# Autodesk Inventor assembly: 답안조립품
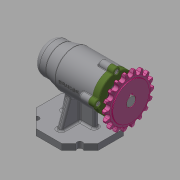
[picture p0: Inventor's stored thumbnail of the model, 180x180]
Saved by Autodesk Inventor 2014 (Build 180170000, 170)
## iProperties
Created: 2021-01
Part Number: 답안조립품
Document SubType Name: Assembly
Designer: kh
Author: kh
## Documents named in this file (12)
- C:\Users\kh\Desktop\710106V1023\답안조립품.iam
- C:\Users\kh\Desktop\710106V1023\본체.ipt
- C:\Users\kh\Desktop\710106V1023\스프로킷.ipt
- C:\Users\kh\Desktop\710106V1023\어댑터슬리브.ipt
- C:\Users\kh\Desktop\710106V1023\오일 실.ipt
- C:\Users\kh\Desktop\710106V1023\축.ipt
- C:\Users\kh\Desktop\710106V1023\커버.ipt
- C:\Users\kh\Desktop\710106V1023\키 5 x 5 x 14.ipt
- C:\Users\kh\Desktop\710106V1023\베어링 6004.ipt
- C:\Users\kh\Desktop\710106V1023\베어링 51202.ipt
- C:\Users\kh\Desktop\710106V1023\볼트 M4.ipt
- C:\Users\kh\Desktop\710106V1023\멈춤나사 M3.ipt
